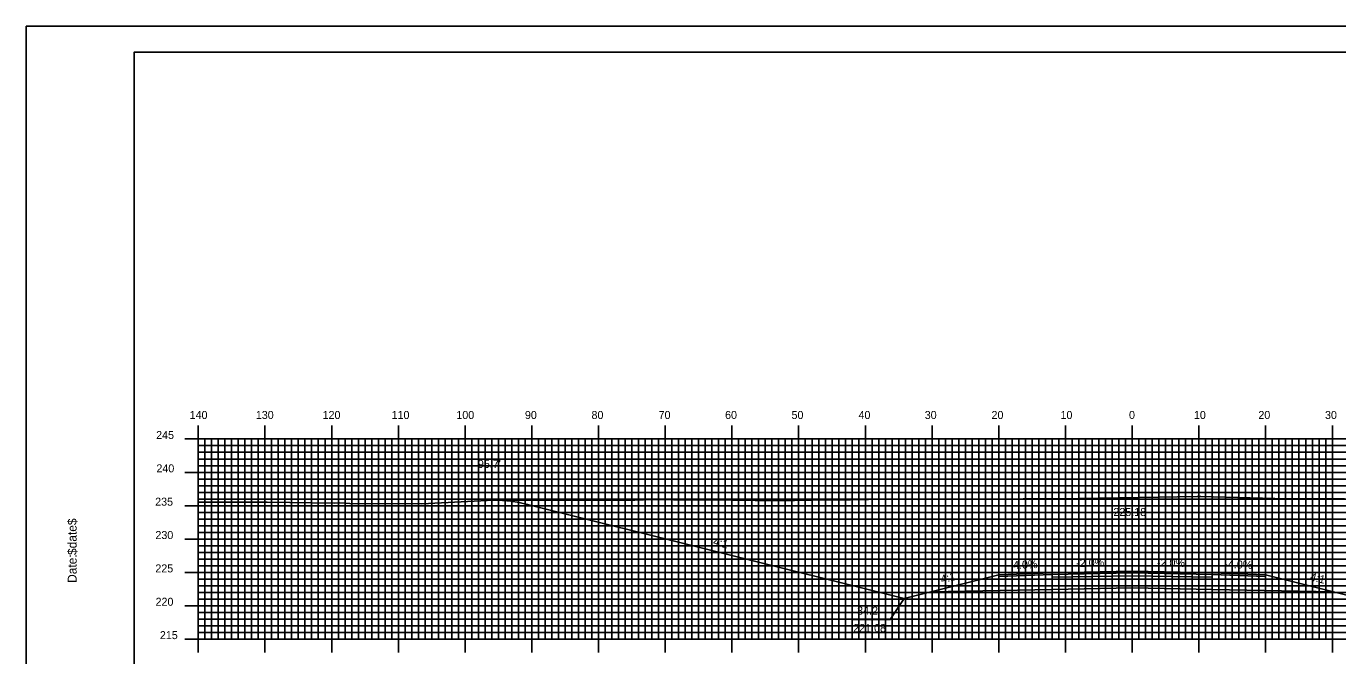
# Model space of a CAD drawing. Extents: x 1802323 to 1802666, y 442591 to 442811.
# Drawn here: x 1802322.8 to 1802519.4, y 442716.2 to 442810.5 of the extents above; entities that cross this region are included whole.
import ezdxf

# ---------------------------------------------------------------- set-up
doc = ezdxf.new("R2010")
doc.units = 0
for name, color, linetype in [('ANNOTATION', 7, 'Continuous'), ('BORDER', 7, 'Continuous'), ('D_Roadway_Centerline', 7, 'Continuous'), ('D_Roadway_Centerline_Text', 7, 'Continuous'), ('D_Roadway_Edge_Shoulder', 7, 'Continuous'), ('D_Roadway_Edge_TW', 7, 'Continuous'), ('D_Roadway_Pavement', 7, 'Continuous'), ('D_Roadway_SlopeLines', 7, 'Continuous'), ('D_Roadway_SubGrade', 7, 'Continuous'), ('D_Text_Standard', 7, 'Continuous'), ('H_V ANNOTATION', 7, 'Continuous'), ('MAJOR', 7, 'Continuous'), ('MINOR', 7, 'Continuous'), ('PLOT BOUNDARY', 7, 'Continuous'), ('S_Roadway_Centerline', 7, 'Continuous')]:
    doc.layers.add(name, color=color, linetype=linetype)

msp = doc.modelspace()

# ---------------------------------------------------------------- linework, layer by layer
at = {"layer": 'ANNOTATION'}
msp.add_lwpolyline([(1802446.63, 442721.6), (1802452.32, 442721.6), (1802454.43, 442724.74)], dxfattribs=at)
at = {"layer": 'BORDER'}
msp.add_lwpolyline([(1802339, 442596.67), (1802659, 442596.67), (1802659, 442806.67), (1802339, 442806.67)], close=True, dxfattribs=at)
at = {"layer": 'D_Roadway_Centerline'}
msp.add_lwpolyline([(1802392.96, 442739.5), (1802394.21, 442739.46), (1802395.46, 442739.33), (1802396.71, 442739.13), (1802397.96, 442738.86), (1802454.43, 442724.74), (1802458.43, 442725.74), (1802468.6, 442728.29), (1802476.6, 442728.61), (1802488.6, 442728.85), (1802500.6, 442728.61), (1802508.6, 442728.29), (1802518.78, 442725.74), (1802522.78, 442724.74), (1802580.4, 442739.15), (1802581.65, 442739.42), (1802582.9, 442739.6), (1802584.15, 442739.69), (1802585.4, 442739.69)], dxfattribs=at)
at = {"layer": 'D_Roadway_Edge_Shoulder'}
for points in [[(1802476.6, 442728.61), (1802468.6, 442728.29), (1802468.6, 442728.04), (1802476.6, 442728.36)], [(1802500.6, 442728.61), (1802508.6, 442728.29), (1802508.6, 442728.04), (1802500.6, 442728.36)]]:
    msp.add_lwpolyline(points, close=True, dxfattribs=at)
at = {"layer": 'D_Roadway_Edge_TW'}
msp.add_lwpolyline([(1802476.6, 442728.36), (1802476.6, 442728.61), (1802488.6, 442728.85), (1802500.6, 442728.61), (1802500.6, 442728.36), (1802488.6, 442728.6)], close=True, dxfattribs=at)
at = {"layer": 'D_Roadway_Pavement'}
msp.add_lwpolyline([(1802476.6, 442727.94), (1802476.6, 442728.36), (1802488.6, 442728.6), (1802500.6, 442728.36), (1802500.6, 442727.94), (1802488.6, 442728.18)], close=True, dxfattribs=at)
at = {"layer": 'D_Roadway_SlopeLines'}
for points in [[(1802454.43, 442724.74), (1802397.96, 442738.86), (1802396.71, 442739.13), (1802395.46, 442739.33), (1802394.21, 442739.46), (1802392.96, 442739.5)], [(1802468.6, 442728.29), (1802454.43, 442724.74)], [(1802508.6, 442728.29), (1802522.78, 442724.74)]]:
    msp.add_lwpolyline(points, dxfattribs=at)
at = {"layer": 'D_Roadway_SubGrade'}
msp.add_lwpolyline([(1802476.6, 442726.11), (1802458.43, 442725.74), (1802468.6, 442728.29), (1802468.6, 442728.04), (1802476.6, 442728.36), (1802488.6, 442728.6), (1802500.6, 442728.36), (1802508.6, 442728.04), (1802508.6, 442728.29), (1802518.78, 442725.74), (1802500.6, 442726.11), (1802488.6, 442726.35)], close=True, dxfattribs=at)
at = {"layer": 'MAJOR'}
for p, q in [((1802348.6, 442750.67), (1802348.6, 442748.67)), ((1802358.6, 442750.67), (1802358.6, 442748.67)), ((1802368.6, 442750.67), (1802368.6, 442748.67)), ((1802378.6, 442750.67), (1802378.6, 442748.67)), ((1802388.6, 442750.67), (1802388.6, 442748.67)), ((1802398.6, 442750.67), (1802398.6, 442748.67)), ((1802408.6, 442750.67), (1802408.6, 442748.67)), ((1802418.6, 442750.67), (1802418.6, 442748.67)), ((1802428.6, 442750.67), (1802428.6, 442748.67)), ((1802438.6, 442750.67), (1802438.6, 442748.67)), ((1802448.6, 442750.67), (1802448.6, 442748.67)), ((1802458.6, 442750.67), (1802458.6, 442748.67)), ((1802468.6, 442750.67), (1802468.6, 442748.67)), ((1802478.6, 442750.67), (1802478.6, 442748.67)), ((1802488.6, 442750.67), (1802488.6, 442748.67)), ((1802498.6, 442750.67), (1802498.6, 442748.67)), ((1802508.6, 442750.67), (1802508.6, 442748.67)), ((1802518.6, 442750.67), (1802518.6, 442748.67)), ((1802346.6, 442748.67), (1802348.6, 442748.67)), ((1802348.6, 442748.67), (1802628.6, 442748.67)), ((1802348.6, 442718.67), (1802348.6, 442748.67)), ((1802348.6, 442718.67), (1802348.6, 442748.67)), ((1802348.6, 442748.67), (1802628.6, 442748.67)), ((1802358.6, 442718.67), (1802358.6, 442748.67)), ((1802368.6, 442718.67), (1802368.6, 442748.67)), ((1802378.6, 442718.67), (1802378.6, 442748.67)), ((1802388.6, 442718.67), (1802388.6, 442748.67)), ((1802398.6, 442718.67), (1802398.6, 442748.67)), ((1802408.6, 442718.67), (1802408.6, 442748.67)), ((1802418.6, 442718.67), (1802418.6, 442748.67)), ((1802428.6, 442718.67), (1802428.6, 442748.67)), ((1802438.6, 442718.67), (1802438.6, 442748.67)), ((1802448.6, 442718.67), (1802448.6, 442748.67)), ((1802458.6, 442718.67), (1802458.6, 442748.67)), ((1802468.6, 442718.67), (1802468.6, 442748.67)), ((1802478.6, 442718.67), (1802478.6, 442748.67)), ((1802488.6, 442718.67), (1802488.6, 442748.67)), ((1802498.6, 442718.67), (1802498.6, 442748.67)), ((1802508.6, 442718.67), (1802508.6, 442748.67)), ((1802518.6, 442718.67), (1802518.6, 442748.67)), ((1802346.6, 442743.67), (1802348.6, 442743.67)), ((1802348.6, 442743.67), (1802628.6, 442743.67)), ((1802346.6, 442738.67), (1802348.6, 442738.67)), ((1802348.6, 442738.67), (1802628.6, 442738.67)), ((1802346.6, 442733.67), (1802348.6, 442733.67)), ((1802348.6, 442733.67), (1802628.6, 442733.67)), ((1802346.6, 442728.67), (1802348.6, 442728.67)), ((1802348.6, 442728.67), (1802628.6, 442728.67)), ((1802346.6, 442723.67), (1802348.6, 442723.67)), ((1802348.6, 442723.67), (1802628.6, 442723.67)), ((1802346.6, 442718.67), (1802348.6, 442718.67)), ((1802348.6, 442718.67), (1802628.6, 442718.67)), ((1802348.6, 442718.67), (1802628.6, 442718.67)), ((1802348.6, 442716.66), (1802348.6, 442718.67)), ((1802358.6, 442716.66), (1802358.6, 442718.67)), ((1802368.6, 442716.66), (1802368.6, 442718.67)), ((1802378.6, 442716.66), (1802378.6, 442718.67)), ((1802388.6, 442716.66), (1802388.6, 442718.67)), ((1802398.6, 442716.66), (1802398.6, 442718.67)), ((1802408.6, 442716.66), (1802408.6, 442718.67)), ((1802418.6, 442716.66), (1802418.6, 442718.67)), ((1802428.6, 442716.66), (1802428.6, 442718.67)), ((1802438.6, 442716.66), (1802438.6, 442718.67)), ((1802448.6, 442716.66), (1802448.6, 442718.67)), ((1802458.6, 442716.66), (1802458.6, 442718.67)), ((1802468.6, 442716.66), (1802468.6, 442718.67)), ((1802478.6, 442716.66), (1802478.6, 442718.67)), ((1802488.6, 442716.66), (1802488.6, 442718.67)), ((1802498.6, 442716.66), (1802498.6, 442718.67)), ((1802508.6, 442716.66), (1802508.6, 442718.67)), ((1802518.6, 442716.66), (1802518.6, 442718.67))]:
    msp.add_line(p, q, dxfattribs=at)
at = {"layer": 'MINOR'}
for p, q in [((1802348.6, 442747.67), (1802628.6, 442747.67)), ((1802348.6, 442747.67), (1802350.61, 442747.67)), ((1802349.6, 442718.67), (1802349.6, 442748.67)), ((1802350.6, 442718.67), (1802350.6, 442748.67)), ((1802351.6, 442718.67), (1802351.6, 442748.67)), ((1802352.6, 442718.67), (1802352.6, 442748.67)), ((1802353.6, 442718.67), (1802353.6, 442748.67)), ((1802354.6, 442718.67), (1802354.6, 442748.67)), ((1802355.6, 442718.67), (1802355.6, 442748.67)), ((1802356.6, 442718.67), (1802356.6, 442748.67)), ((1802357.6, 442718.67), (1802357.6, 442748.67)), ((1802359.6, 442718.67), (1802359.6, 442748.67)), ((1802360.6, 442718.67), (1802360.6, 442748.67)), ((1802361.6, 442718.67), (1802361.6, 442748.67)), ((1802362.6, 442718.67), (1802362.6, 442748.67)), ((1802363.6, 442718.67), (1802363.6, 442748.67)), ((1802364.6, 442718.67), (1802364.6, 442748.67)), ((1802365.6, 442718.67), (1802365.6, 442748.67)), ((1802366.6, 442718.67), (1802366.6, 442748.67)), ((1802367.6, 442718.67), (1802367.6, 442748.67)), ((1802369.6, 442718.67), (1802369.6, 442748.67)), ((1802370.6, 442718.67), (1802370.6, 442748.67)), ((1802371.6, 442718.67), (1802371.6, 442748.67)), ((1802372.6, 442718.67), (1802372.6, 442748.67)), ((1802373.6, 442718.67), (1802373.6, 442748.67)), ((1802374.6, 442718.67), (1802374.6, 442748.67)), ((1802375.6, 442718.67), (1802375.6, 442748.67)), ((1802376.6, 442718.67), (1802376.6, 442748.67)), ((1802377.6, 442718.67), (1802377.6, 442748.67)), ((1802379.6, 442718.67), (1802379.6, 442748.67)), ((1802380.6, 442718.67), (1802380.6, 442748.67)), ((1802381.6, 442718.67), (1802381.6, 442748.67)), ((1802382.6, 442718.67), (1802382.6, 442748.67)), ((1802383.6, 442718.67), (1802383.6, 442748.67)), ((1802384.6, 442718.67), (1802384.6, 442748.67)), ((1802385.6, 442718.67), (1802385.6, 442748.67)), ((1802386.6, 442718.67), (1802386.6, 442748.67)), ((1802387.6, 442718.67), (1802387.6, 442748.67)), ((1802389.6, 442718.67), (1802389.6, 442748.67)), ((1802390.6, 442718.67), (1802390.6, 442748.67)), ((1802391.6, 442718.67), (1802391.6, 442748.67)), ((1802392.6, 442718.67), (1802392.6, 442748.67)), ((1802393.6, 442718.67), (1802393.6, 442748.67)), ((1802394.6, 442718.67), (1802394.6, 442748.67)), ((1802395.6, 442718.67), (1802395.6, 442748.67)), ((1802396.6, 442718.67), (1802396.6, 442748.67)), ((1802397.6, 442718.67), (1802397.6, 442748.67)), ((1802399.6, 442718.67), (1802399.6, 442748.67)), ((1802400.6, 442718.67), (1802400.6, 442748.67)), ((1802401.6, 442718.67), (1802401.6, 442748.67)), ((1802402.6, 442718.67), (1802402.6, 442748.67)), ((1802403.6, 442718.67), (1802403.6, 442748.67)), ((1802404.6, 442718.67), (1802404.6, 442748.67)), ((1802405.6, 442718.67), (1802405.6, 442748.67)), ((1802406.6, 442718.67), (1802406.6, 442748.67)), ((1802407.6, 442718.67), (1802407.6, 442748.67)), ((1802409.6, 442718.67), (1802409.6, 442748.67)), ((1802410.6, 442718.67), (1802410.6, 442748.67)), ((1802411.6, 442718.67), (1802411.6, 442748.67)), ((1802412.6, 442718.67), (1802412.6, 442748.67)), ((1802413.6, 442718.67), (1802413.6, 442748.67)), ((1802414.6, 442718.67), (1802414.6, 442748.67)), ((1802415.6, 442718.67), (1802415.6, 442748.67)), ((1802416.6, 442718.67), (1802416.6, 442748.67)), ((1802417.6, 442718.67), (1802417.6, 442748.67)), ((1802419.6, 442718.67), (1802419.6, 442748.67)), ((1802420.6, 442718.67), (1802420.6, 442748.67)), ((1802421.6, 442718.67), (1802421.6, 442748.67)), ((1802422.6, 442718.67), (1802422.6, 442748.67)), ((1802423.6, 442718.67), (1802423.6, 442748.67)), ((1802424.6, 442718.67), (1802424.6, 442748.67)), ((1802425.6, 442718.67), (1802425.6, 442748.67)), ((1802426.6, 442718.67), (1802426.6, 442748.67)), ((1802427.6, 442718.67), (1802427.6, 442748.67)), ((1802429.6, 442718.67), (1802429.6, 442748.67)), ((1802430.6, 442718.67), (1802430.6, 442748.67)), ((1802431.6, 442718.67), (1802431.6, 442748.67)), ((1802432.6, 442718.67), (1802432.6, 442748.67)), ((1802433.6, 442718.67), (1802433.6, 442748.67)), ((1802434.6, 442718.67), (1802434.6, 442748.67)), ((1802435.6, 442718.67), (1802435.6, 442748.67)), ((1802436.6, 442718.67), (1802436.6, 442748.67)), ((1802437.6, 442718.67), (1802437.6, 442748.67)), ((1802439.6, 442718.67), (1802439.6, 442748.67)), ((1802440.6, 442718.67), (1802440.6, 442748.67)), ((1802441.6, 442718.67), (1802441.6, 442748.67)), ((1802442.6, 442718.67), (1802442.6, 442748.67)), ((1802443.6, 442718.67), (1802443.6, 442748.67)), ((1802444.6, 442718.67), (1802444.6, 442748.67)), ((1802445.6, 442718.67), (1802445.6, 442748.67)), ((1802446.6, 442718.67), (1802446.6, 442748.67)), ((1802447.6, 442718.67), (1802447.6, 442748.67)), ((1802449.6, 442718.67), (1802449.6, 442748.67)), ((1802450.6, 442718.67), (1802450.6, 442748.67)), ((1802451.6, 442718.67), (1802451.6, 442748.67)), ((1802452.6, 442718.67), (1802452.6, 442748.67)), ((1802453.6, 442718.67), (1802453.6, 442748.67)), ((1802454.6, 442718.67), (1802454.6, 442748.67)), ((1802455.6, 442718.67), (1802455.6, 442748.67)), ((1802456.6, 442718.67), (1802456.6, 442748.67)), ((1802457.6, 442718.67), (1802457.6, 442748.67)), ((1802459.6, 442718.67), (1802459.6, 442748.67)), ((1802460.6, 442718.67), (1802460.6, 442748.67)), ((1802461.6, 442718.67), (1802461.6, 442748.67)), ((1802462.6, 442718.67), (1802462.6, 442748.67)), ((1802463.6, 442718.67), (1802463.6, 442748.67)), ((1802464.6, 442718.67), (1802464.6, 442748.67)), ((1802465.6, 442718.67), (1802465.6, 442748.67)), ((1802466.6, 442718.67), (1802466.6, 442748.67)), ((1802467.6, 442718.67), (1802467.6, 442748.67)), ((1802469.6, 442718.67), (1802469.6, 442748.67)), ((1802470.6, 442718.67), (1802470.6, 442748.67)), ((1802471.6, 442718.67), (1802471.6, 442748.67)), ((1802472.6, 442718.67), (1802472.6, 442748.67)), ((1802473.6, 442718.67), (1802473.6, 442748.67)), ((1802474.6, 442718.67), (1802474.6, 442748.67)), ((1802475.6, 442718.67), (1802475.6, 442748.67)), ((1802476.6, 442718.67), (1802476.6, 442748.67)), ((1802477.6, 442718.67), (1802477.6, 442748.67)), ((1802479.6, 442718.67), (1802479.6, 442748.67)), ((1802480.6, 442718.67), (1802480.6, 442748.67)), ((1802481.6, 442718.67), (1802481.6, 442748.67)), ((1802482.6, 442718.67), (1802482.6, 442748.67)), ((1802483.6, 442718.67), (1802483.6, 442748.67)), ((1802484.6, 442718.67), (1802484.6, 442748.67)), ((1802485.6, 442718.67), (1802485.6, 442748.67)), ((1802486.6, 442718.67), (1802486.6, 442748.67)), ((1802487.6, 442718.67), (1802487.6, 442748.67)), ((1802489.6, 442718.67), (1802489.6, 442748.67)), ((1802490.6, 442718.67), (1802490.6, 442748.67)), ((1802491.6, 442718.67), (1802491.6, 442748.67)), ((1802492.6, 442718.67), (1802492.6, 442748.67)), ((1802493.6, 442718.67), (1802493.6, 442748.67)), ((1802494.6, 442718.67), (1802494.6, 442748.67)), ((1802495.6, 442718.67), (1802495.6, 442748.67)), ((1802496.6, 442718.67), (1802496.6, 442748.67)), ((1802497.6, 442718.67), (1802497.6, 442748.67)), ((1802499.6, 442718.67), (1802499.6, 442748.67)), ((1802500.6, 442718.67), (1802500.6, 442748.67)), ((1802501.6, 442718.67), (1802501.6, 442748.67)), ((1802502.6, 442718.67), (1802502.6, 442748.67)), ((1802503.6, 442718.67), (1802503.6, 442748.67)), ((1802504.6, 442718.67), (1802504.6, 442748.67)), ((1802505.6, 442718.67), (1802505.6, 442748.67)), ((1802506.6, 442718.67), (1802506.6, 442748.67)), ((1802507.6, 442718.67), (1802507.6, 442748.67)), ((1802509.6, 442718.67), (1802509.6, 442748.67)), ((1802510.6, 442718.67), (1802510.6, 442748.67)), ((1802511.6, 442718.67), (1802511.6, 442748.67)), ((1802512.6, 442718.67), (1802512.6, 442748.67)), ((1802513.6, 442718.67), (1802513.6, 442748.67)), ((1802514.6, 442718.67), (1802514.6, 442748.67)), ((1802515.6, 442718.67), (1802515.6, 442748.67)), ((1802516.6, 442718.67), (1802516.6, 442748.67)), ((1802517.6, 442718.67), (1802517.6, 442748.67)), ((1802348.6, 442746.67), (1802628.6, 442746.67)), ((1802348.6, 442746.67), (1802350.61, 442746.67)), ((1802348.6, 442745.67), (1802628.6, 442745.67)), ((1802348.6, 442745.67), (1802350.61, 442745.67)), ((1802348.6, 442744.67), (1802628.6, 442744.67)), ((1802348.6, 442744.67), (1802350.61, 442744.67)), ((1802348.6, 442742.67), (1802628.6, 442742.67)), ((1802348.6, 442742.67), (1802350.61, 442742.67)), ((1802348.6, 442741.67), (1802628.6, 442741.67)), ((1802348.6, 442741.67), (1802350.61, 442741.67)), ((1802348.6, 442740.67), (1802628.6, 442740.67)), ((1802348.6, 442740.67), (1802350.61, 442740.67)), ((1802348.6, 442739.67), (1802628.6, 442739.67)), ((1802348.6, 442739.67), (1802350.61, 442739.67)), ((1802348.6, 442737.67), (1802628.6, 442737.67)), ((1802348.6, 442737.67), (1802350.61, 442737.67)), ((1802348.6, 442736.67), (1802628.6, 442736.67)), ((1802348.6, 442736.67), (1802350.61, 442736.67)), ((1802348.6, 442735.67), (1802628.6, 442735.67)), ((1802348.6, 442735.67), (1802350.61, 442735.67)), ((1802348.6, 442734.67), (1802628.6, 442734.67)), ((1802348.6, 442734.67), (1802350.61, 442734.67)), ((1802348.6, 442732.67), (1802628.6, 442732.67)), ((1802348.6, 442732.67), (1802350.61, 442732.67)), ((1802348.6, 442731.67), (1802628.6, 442731.67)), ((1802348.6, 442731.67), (1802350.61, 442731.67)), ((1802348.6, 442730.67), (1802628.6, 442730.67)), ((1802348.6, 442730.67), (1802350.61, 442730.67)), ((1802348.6, 442729.67), (1802628.6, 442729.67)), ((1802348.6, 442729.67), (1802350.61, 442729.67)), ((1802348.6, 442727.67), (1802628.6, 442727.67)), ((1802348.6, 442727.67), (1802350.61, 442727.67)), ((1802348.6, 442726.67), (1802628.6, 442726.67)), ((1802348.6, 442726.67), (1802350.61, 442726.67)), ((1802348.6, 442725.67), (1802628.6, 442725.67)), ((1802348.6, 442725.67), (1802350.61, 442725.67)), ((1802348.6, 442724.67), (1802628.6, 442724.67)), ((1802348.6, 442724.67), (1802350.61, 442724.67)), ((1802348.6, 442722.67), (1802628.6, 442722.67)), ((1802348.6, 442722.67), (1802350.61, 442722.67)), ((1802348.6, 442721.67), (1802628.6, 442721.67)), ((1802348.6, 442721.67), (1802350.61, 442721.67)), ((1802348.6, 442720.67), (1802628.6, 442720.67)), ((1802348.6, 442720.67), (1802350.61, 442720.67)), ((1802348.6, 442719.67), (1802628.6, 442719.67)), ((1802348.6, 442719.67), (1802350.61, 442719.67))]:
    msp.add_line(p, q, dxfattribs=at)
at = {"layer": 'PLOT BOUNDARY'}
msp.add_lwpolyline([(1802322.81, 442590.55), (1802662.81, 442590.55), (1802662.81, 442810.55), (1802322.81, 442810.55)], close=True, dxfattribs=at)
at = {"layer": 'S_Roadway_Centerline'}
msp.add_lwpolyline([(1802348.6, 442739.21), (1802350.1, 442739.18), (1802358.93, 442739.22), (1802369.09, 442739.07), (1802369.78, 442739.08), (1802371.34, 442739.02), (1802382.11, 442738.94), (1802392.9, 442739.5), (1802394.89, 442739.49), (1802414.06, 442739.5), (1802416.65, 442739.61), (1802419.84, 442739.57), (1802428.63, 442739.5), (1802435.47, 442739.4), (1802440.51, 442739.49), (1802446.37, 442739.54), (1802451.75, 442739.65), (1802456.38, 442739.62), (1802472.23, 442739.7), (1802475.33, 442739.71), (1802477.79, 442739.72), (1802498.36, 442740.06), (1802498.9, 442740.06), (1802509.99, 442739.73), (1802520.4, 442739.7)], dxfattribs=at)

# ---------------------------------------------------------------- texts
at = {"layer": 'ANNOTATION'}
for s, rotation, p in [('4:1', 345.9638, (1802425.7, 442732.79)), ('-4.0%', 2.2906, (1802470.23, 442729.15)), ('-2.0%', 1.1458, (1802480.21, 442729.48)), ('-2.0%', 358.8542, (1802492.29, 442729.57)), ('-4.0%', 357.7094, (1802502.39, 442729.34)), ('4:1', 14.0362, (1802460.05, 442727.01)), ('4:1', 345.9638, (1802515.19, 442727.5))]:
    msp.add_text(s, height=1.2, rotation=rotation, dxfattribs=at).set_placement(p)
for s, p in [("34.2'", (1802447.37, 442722.33)), ('221.08', (1802446.78, 442719.73))]:
    msp.add_text(s, height=1.2, dxfattribs=at).set_placement(p)
at = {"layer": 'BORDER'}
for s, p in [('$date$', (1802330.37, 442731.28)), ('Date:', (1802330.37, 442727.1))]:
    msp.add_text(s, height=1.339, rotation=90, dxfattribs=at).set_placement(p)
at = {"layer": 'D_Roadway_Centerline'}
for s, p in [('C', (1802488.6, 442728.85)), ('L', (1802488.6, 442728.84))]:
    msp.add_text(s, height=0.0146, dxfattribs=at).set_placement(p)
at = {"layer": 'D_Roadway_Centerline_Text'}
msp.add_text('225.18', height=1.2, dxfattribs=at).set_placement((1802485.78, 442737.12))
at = {"layer": 'D_Text_Standard'}
msp.add_text("95.7'", height=1.2, dxfattribs=at).set_placement((1802390.52, 442744.33))
at = {"layer": 'H_V ANNOTATION'}
for s, p in [('140', (1802347.31, 442751.67)), ('130', (1802357.23, 442751.67)), ('120', (1802367.24, 442751.67)), ('110', (1802377.58, 442751.67)), ('100', (1802387.29, 442751.67)), ('90', (1802397.57, 442751.67)), ('80', (1802407.55, 442751.67)), ('70', (1802417.61, 442751.67)), ('60', (1802427.57, 442751.67)), ('50', (1802437.53, 442751.67)), ('40', (1802447.57, 442751.67)), ('30', (1802457.5, 442751.67)), ('20', (1802467.51, 442751.67)), ('10', (1802477.85, 442751.67)), ('0', (1802488.12, 442751.67)), ('10', (1802497.85, 442751.67)), ('20', (1802507.51, 442751.67)), ('30', (1802517.5, 442751.67)), ('245', (1802342.29, 442748.67)), ('240', (1802342.33, 442743.67)), ('235', (1802342.14, 442738.67)), ('230', (1802342.18, 442733.67)), ('225', (1802342.17, 442728.67)), ('220', (1802342.2, 442723.67)), ('215', (1802342.85, 442718.67))]:
    msp.add_text(s, height=1.2, dxfattribs=at).set_placement(p)
at = {"layer": 'MAJOR'}
msp.add_text('-', height=0.012, dxfattribs=at).set_placement((1802348.59, 442718.67))

doc.saveas('drawing.dxf')
